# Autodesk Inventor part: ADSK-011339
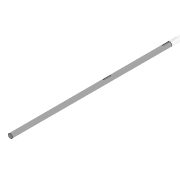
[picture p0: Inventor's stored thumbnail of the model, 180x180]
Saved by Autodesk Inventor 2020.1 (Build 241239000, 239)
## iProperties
Created: 1999-12
Part Number: ADSK-011339
Material: Acier doux
Description: SHFT-T,TH,GX,07-06,273,ADJUST,WIDTH,LH
Document SubType Name: Modeling
Designer: sspink
Density: 7.86 g/cm^3
Appearance: Chrom - poliert
Mass: 1741.91 g
Surface Area: 451.295 cm^2
Volume: 221.617 cm^3
Control State: 0
Master: False
Checked Out: False
Shininess: 0.0
Length Units: 11269
Angle Units: 11279
Time Units: 11290
Mass Units: 11283
Length Display Precision: 3
Angle Display Precision: 2
Compacted: True
CUTLENGTH: 27.38
MATERIAL DESC: THREADED-ROD,0.750-06 LH ACME
MATERIAL_NUMBER: A084662
Dimensions: 20x20x707 mm
Mass: 1,742 kg
DocNumber: ADSK-011339.ipt
Folder: 01 - Themengebiete\Simplification\01 - Packaging machine\
VDS_Category: 3D Komponenten
Density: 0.0
Volumn: 0.0
Area: 0.0
PropertySet Name: Model Information
Author: sspink
Revision Number: -
Title: shaft
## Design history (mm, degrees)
node "Solide1"
  node "Extrusion1" dims "d1" = 707, "d2" = 0
  node "Extrusion2" dims "d6" = 32, "d7" = 0
  node "Extrusion3" dims "d9" = 32, "d10" = 0
sketch "Sketch1"
  geometry: C1 r 10 at (0, 0); 1 further point
  constraints: 1 centre point, 1 coincident
  dimensions: "d0" = 20 diameter of C1
sketch "Sketch2"
  geometry: L1 (0, 0)-(0, 8.5); L2 (-2.5, 9.682)-(-2.5, 8.5); L3 (2.5, 8.5)-(2.5, 9.682); L4 (-2.5, 8.5)-(2.5, 8.5); A1 r 10 centre (0, 0) between (-2.5, 9.682) and (2.5, 9.682) reference
  constraints: 8 end point, 2 point on circle, 1 horizontal, 1 midpoint, 1 parallel, 1 vertical
  dimensions: "d3" = 8.5 distance of L1.end L1.start; "d4" = 5 distance between parallel lines of L3 L2
workplane "Work Plane1"
sketch "Sketch3"
  geometry: L1 (-2.5, 8.5)-(2.5, 8.5) reference; L2 (2.5, 8.5)-(2.5, 9.682) reference; L3 (-2.5, 9.682)-(-2.5, 8.5) reference; A1 r 10 centre (0, 0) between (2.5, 9.682) and (-2.5, 9.682) reference
  node "Projizierte Kontur1"
chamfer "Fase1" distance "d11" = 1; stored, may be unused: second distance "d12" = 2, angle "d13" = 45 deg
fillet "Rundung1"
fillet "Rundung2"
fillet "Rundung3"
node "Corps solides"
node "Corps surfaciques"
other parameters: "d8" = -278
